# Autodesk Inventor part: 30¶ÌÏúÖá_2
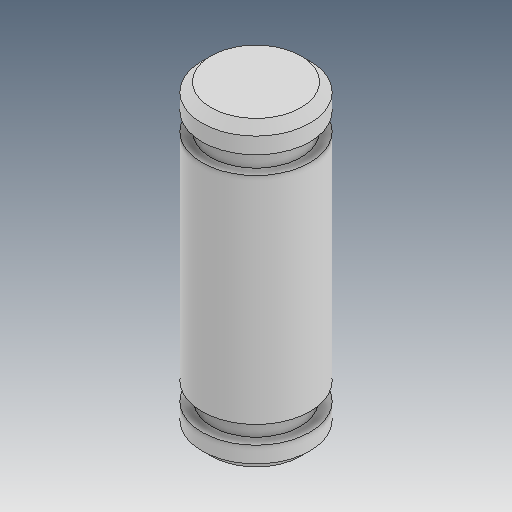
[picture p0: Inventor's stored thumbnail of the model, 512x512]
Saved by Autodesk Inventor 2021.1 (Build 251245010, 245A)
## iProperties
Created: 2019-04
Part Number: 30¶ÌÏúÖá_2
Material: Ogólny
Document SubType Name: Modeling
Designer: user
Density: 1 g/cm^3
Appearance: Domyślna
Author: user
Revision Number: ÈÎºÎ
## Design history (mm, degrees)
feature "ÊäÈë1"
node "Bryła1"
